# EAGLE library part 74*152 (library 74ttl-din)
Data SELECTOR/MULTIPLEXER
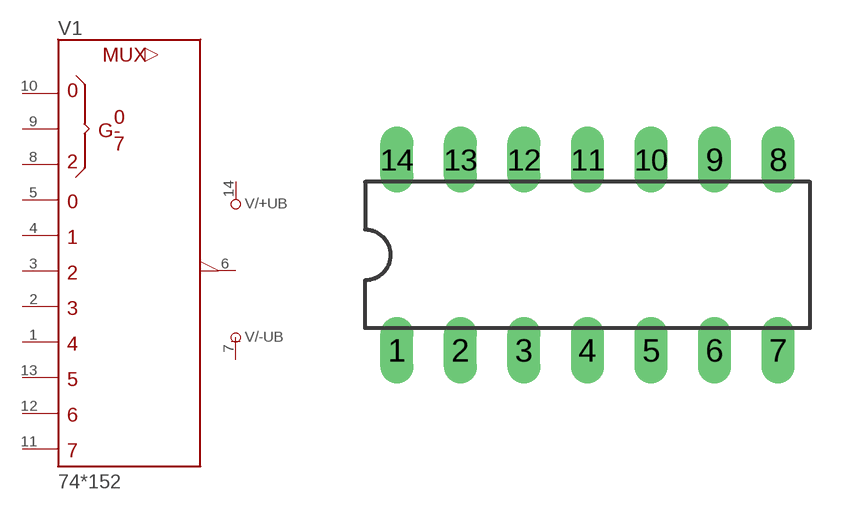
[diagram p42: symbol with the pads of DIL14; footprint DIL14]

Designator prefix V; gates /+UB=+UB /-UB=-UB 1=152

## 74152N  [DIL14]
1  1:D4  in
2  1:D3  in
3  1:D2  in
4  1:D1  in
5  1:D0  in
6  1:W  out
7  /-UB:-UB  pwr
8  1:C  in
9  1:B  in
10  1:A  in
11  1:D7  in
12  1:D6  in
13  1:D5  in
14  /+UB:+UB  pwr

## Footprint DIL14 (pad centres in mm)
Dual In Line Package
drill 0.813 long: 1 -7.62,-3.81; 2 -5.08,-3.81; 3 -2.54,-3.81; 4 0,-3.81; 5 2.54,-3.81; 6 5.08,-3.81; 7 7.62,-3.81; 8 7.62,3.81; 9 5.08,3.81; 10 2.54,3.81; 11 0,3.81; 12 -2.54,3.81; 13 -5.08,3.81; 14 -7.62,3.81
